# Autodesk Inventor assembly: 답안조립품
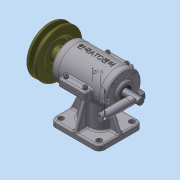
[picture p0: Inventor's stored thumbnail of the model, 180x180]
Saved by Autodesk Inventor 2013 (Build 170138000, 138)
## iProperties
Created: 2015-05
Part Number: 답안조립품
Document SubType Name: Assembly
Designer: Administrator
Author: Administrator
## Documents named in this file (18)
- C:\Users\Administrator\Desktop\350508V1009\답안조립품.iam
- C:\Users\Administrator\Desktop\350508V1009\본체.ipt
- C:\Users\Administrator\Desktop\350508V1009\편심축.ipt
- C:\Users\Administrator\Desktop\350508V1009\베어링 6201.ipt
- C:\Users\Administrator\Desktop\350508V1009\베어링 6202.ipt
- C:\Users\Administrator\Desktop\350508V1009\앞커버.ipt
- C:\Users\Administrator\Desktop\350508V1009\뒤커버.ipt
- C:\Users\Administrator\Desktop\350508V1009\오일실.ipt
- C:\Users\Administrator\Desktop\350508V1009\V-벨트풀리.ipt
- C:\Users\Administrator\Desktop\350508V1009\키4x4.ipt
- C:\Users\Administrator\Desktop\350508V1009\멈춤나사.ipt
- C:\Users\Administrator\Desktop\350508V1009\링크.ipt
- C:\Users\Administrator\Desktop\350508V1009\너트 M8.ipt
- C:\Users\Administrator\Desktop\350508V1009\본체 커버.ipt
- C:\Users\Administrator\Desktop\350508V1009\M4x0.5x14.ipt
- C:\Users\Administrator\Desktop\350508V1009\M3x0.5x8.ipt
- C:\Users\Administrator\Desktop\350508V1009\슬라이드.ipt
- C:\Users\Administrator\Desktop\350508V1009\스프링.ipt
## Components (14 placed, 4 different names)
1. V-벨트풀리:1 — 플러쉬:1
2. KS B 1012 C - 미터 C M8:1
3. M4x0.5x14:1
4. M4x0.5x14:2
5. M4x0.5x14:3
6. M4x0.5x14:4
7. M3x0.5x8:3
8. M3x0.5x8:4
9. M3x0.5x8:5
10. M3x0.5x8:6
11. M3x0.5x8:7
12. M3x0.5x8:8
13. M3x0.5x8:9
14. M3x0.5x8:10
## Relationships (1: Flush 1)
- 플러쉬:1 [Flush]: V-벨트풀리:1
